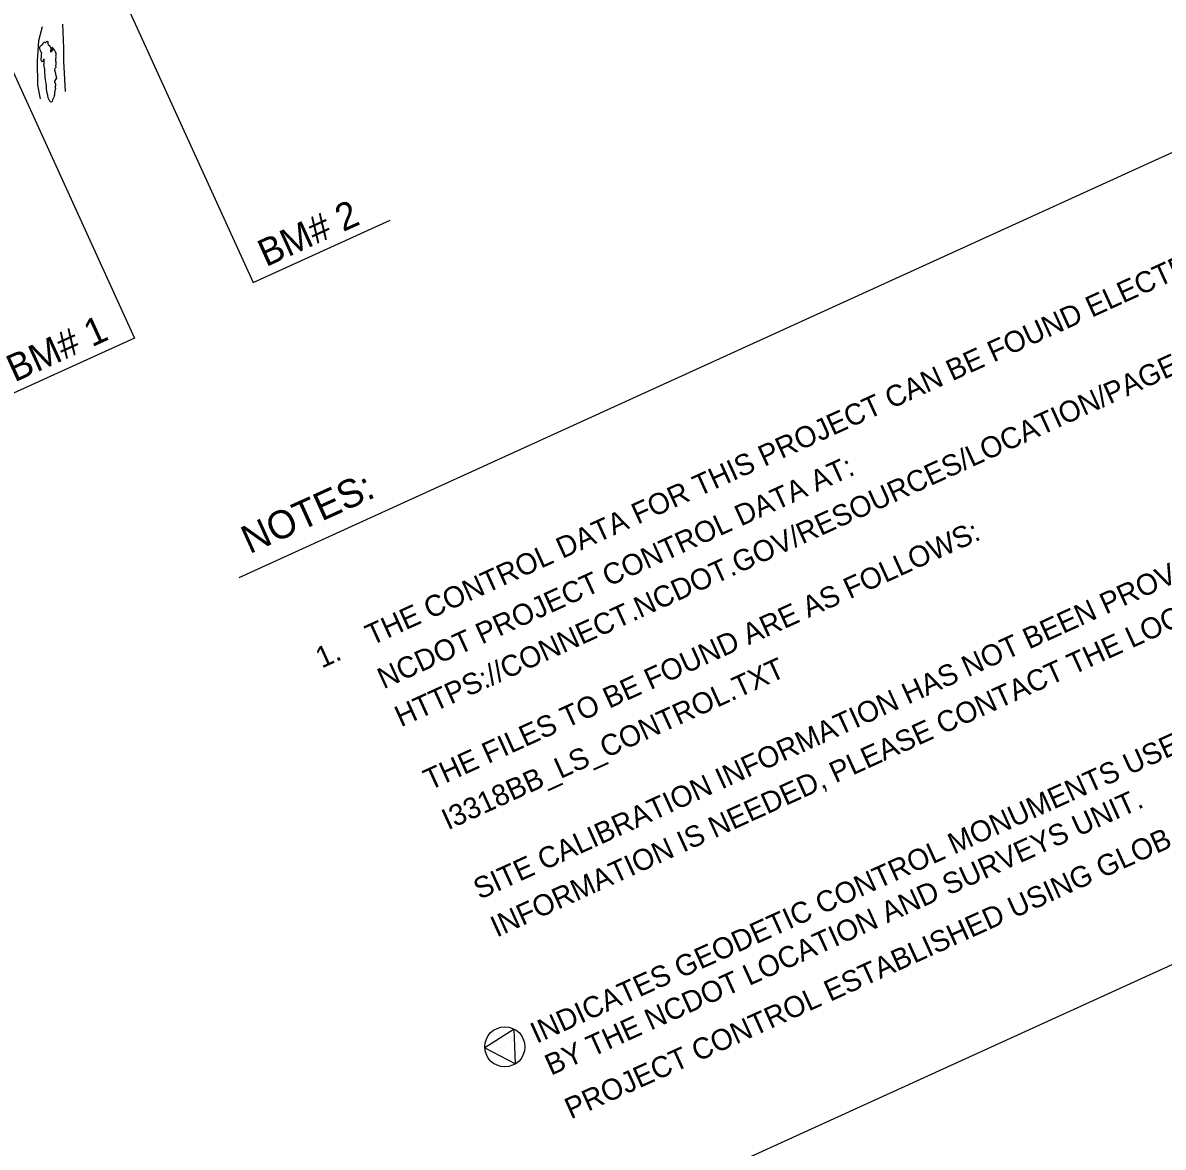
# Model space of a CAD drawing. Extents: x 2243531 to 2252747, y 658714 to 667210.
# Drawn here: x 2248974 to 2251073, y 661192 to 663262 of the extents above; entities that cross this region are included whole.
import ezdxf

# ---------------------------------------------------------------- set-up
doc = ezdxf.new("R2010")
doc.units = 0
for name, color, linetype in [('CTL Bench Mark Text', 7, 'Continuous'), ('CTL NGS Horizontal CELL', 7, 'Continuous'), ('CTL Sheet Border CELL', 7, 'Continuous'), ('CTL Sheet Notes CELL', 7, 'Continuous'), ('Exist Hydro Stream or Body of Water', 7, 'Continuous')]:
    doc.layers.add(name, color=color, linetype=linetype)

msp = doc.modelspace()

# ---------------------------------------------------------------- linework, layer by layer
at = {"layer": 'CTL NGS Horizontal CELL'}
for p, q in [((2249125.6, 663382.5), (2249398.3, 662784)), ((2248916.3, 663259.8), (2249179.7, 662681.7)), ((2249398.3, 662784), (2249650.2, 662898.7)), ((2249179.7, 662681.7), (2248943.9, 662574.3)), ((2249861.4, 661377.1), (2249861.4, 661377.1))]:
    msp.add_line(p, q, dxfattribs=at)
msp.add_lwpolyline([(2249824.5, 661375.2), (2249881.2, 661346), (2249878.3, 661409.9), (2249824.5, 661375.2)], dxfattribs=at)
msp.add_circle((2249861.4, 661377.1), 36.9, dxfattribs=at)
at = {"layer": 'CTL Sheet Border CELL'}
msp.add_lwpolyline([(2250569.7, 667061), (2243744.8, 663951.1), (2245921.8, 659173.7), (2252746.6, 662283.7)], close=True, dxfattribs=at)
at = {"layer": 'CTL Sheet Notes CELL'}
msp.add_line((2249372.3, 662241), (2251851.4, 663370.7), dxfattribs=at)
at = {"layer": 'Exist Hydro Stream or Body of Water'}
for points in [[(2249010.2, 663254.4), (2249003.4, 663229), (2249000.8, 663192), (2249001.5, 663147.2), (2249006.3, 663121.8)], [(2249052.9, 663135.6), (2249049.9, 663191.3), (2249050.1, 663215.3), (2249047.9, 663259.6)], [(2249036.1, 663160), (2249035.2, 663158.5), (2249034.3, 663157.6), (2249033.5, 663155.9), (2249032.7, 663154.1), (2249033, 663152.5), (2249033.8, 663151.1), (2249034.6, 663149.8), (2249034.6, 663148.4), (2249034.6, 663146.8), (2249034, 663144.9), (2249033.9, 663142.6), (2249034.3, 663141), (2249034.2, 663138.8), (2249033.4, 663137.3), (2249033.1, 663135.7), (2249032.7, 663133.6), (2249032.6, 663131.4), (2249032.6, 663129.5), (2249032.2, 663127.7), (2249031.3, 663125.3), (2249030.3, 663122.6), (2249029.3, 663120), (2249028.4, 663118), (2249027.5, 663116.5), (2249026.1, 663115.7), (2249024.3, 663117.6), (2249022.7, 663120.4), (2249021.3, 663123.6), (2249020.6, 663128.5), (2249019, 663132.6), (2249018.4, 663136.8), (2249018.2, 663140.1), (2249018.2, 663143.7), (2249017.8, 663146.6), (2249017.1, 663150.5), (2249016.6, 663154.2), (2249015.9, 663157.8), (2249015.3, 663161.5), (2249015.3, 663164.9), (2249015.2, 663169), (2249015.1, 663172.4), (2249014.7, 663175.9), (2249014.5, 663179.2), (2249013.7, 663182.3), (2249013.3, 663184.6), (2249013.7, 663186.6), (2249013.7, 663189.2), (2249013.7, 663191.1), (2249013.9, 663192.9), (2249013.8, 663194.5), (2249013.4, 663195), (2249012.5, 663194.4), (2249011.8, 663192.4), (2249011.1, 663190.8), (2249010.3, 663190.2), (2249009.5, 663190.9), (2249008.4, 663193.4), (2249008.3, 663196.3), (2249008.5, 663199.4), (2249008.9, 663203.2), (2249009.1, 663205.9), (2249008.3, 663208.2), (2249007.2, 663210.1), (2249006.5, 663212.2), (2249005.9, 663214.5), (2249006, 663217.4), (2249007, 663219.6), (2249009.2, 663221.1), (2249010.7, 663222.1), (2249011.7, 663223.7), (2249012.4, 663225.3), (2249013.8, 663226.4), (2249014.8, 663226.6), (2249015.6, 663225.5), (2249016.4, 663225.5), (2249017.2, 663226.6), (2249018.1, 663227.5), (2249018.9, 663228), (2249019.5, 663228), (2249020.3, 663226.1), (2249020.5, 663224.1), (2249021, 663221.6), (2249021.7, 663220.6), (2249022.7, 663220.1), (2249023.5, 663219.3), (2249024.5, 663218), (2249025.4, 663216.3), (2249025.7, 663214.2), (2249025.7, 663212.3), (2249025.4, 663211.2), (2249025.2, 663209.7), (2249025.6, 663208.8), (2249026.9, 663208.9), (2249028.1, 663209.8), (2249028.7, 663211.2), (2249029, 663212.7), (2249028.8, 663214.8), (2249028.5, 663216.9), (2249029.5, 663216), (2249031.1, 663213.3), (2249032.2, 663211.5), (2249033.1, 663210.1), (2249034.2, 663208.2), (2249035.2, 663205.9), (2249035.4, 663204.1), (2249035.2, 663202.1), (2249034.8, 663200.6), (2249035.3, 663198.7), (2249035.3, 663197.1), (2249034.8, 663195.6), (2249034.4, 663194), (2249034.4, 663192.2), (2249034.9, 663190.3), (2249035.4, 663188.4), (2249035.3, 663186.5), (2249034.9, 663184.8), (2249034.7, 663183.4), (2249035, 663181), (2249034.9, 663179.5), (2249034.2, 663178.6), (2249033.4, 663177.1), (2249033, 663175), (2249033.4, 663173), (2249034, 663171), (2249034.6, 663169.3), (2249034.7, 663167), (2249035, 663165.7), (2249035.5, 663163.8), (2249035.7, 663161.8), (2249036.1, 663160)]]:
    msp.add_lwpolyline(points, dxfattribs=at)

# ---------------------------------------------------------------- texts
at = {"layer": 'CTL Bench Mark Text'}
for s, p in [('BM# 2', (2249421.8, 662812)), ('BM# 1', (2248959.3, 662599.8))]:
    msp.add_text(s, height=50, rotation=24.4979, dxfattribs=at).set_placement(p)
at = {"layer": 'CTL Sheet Notes CELL'}
for s, height, rotation, p in [('1.    THE CONTROL DATA FOR THIS PROJECT CAN BE FOUND ELECTRONICALLY BY SELECTING', 38.739, 24.4979, (2249524.4, 662073.3)), ('HTTPS://CONNECT.NCDOT.GOV/RESOURCES/LOCATION/PAGES/DEFAULT.ASPX', 38.739, 24.4979, (2249670.1, 661965.2)), ('SITE CALIBRATION INFORMATION HAS NOT BEEN PROVIDED FOR THIS PROJECT. IF FURTHER', 38.739, 24.4979, (2249814.9, 661647.6)), ('INFORMATION IS NEEDED, PLEASE CONTACT THE LOCATION AND SURVEYS UNIT.', 38.739, 24.4979, (2249846.5, 661578.1)), ('NCDOT PROJECT CONTROL DATA AT:', 38.739, 24.4979, (2249638.3, 662035.1)), ('INDICATES GEODETIC CONTROL MONUMENTS USED OR SET FOR HORIZONTAL PROJECT CONTROL', 38.739, 24.3927, (2249919.9, 661382.5)), ('NOTES:', 51.65, 24.3927, (2249391.6, 662283.7)), ('THE FILES TO BE FOUND ARE AS FOLLOWS:', 38.739, 24.4979, (2249723.2, 661848.7)), ('I3318BB_LS_CONTROL.TXT', 38.739, 24.4979, (2249756.6, 661775.5)), ('PROJECT CONTROL ESTABLISHED USING GLOBAL POSITIONING SYSTEM.', 38.739, 24.3927, (2249982.9, 661243.5)), ('BY THE NCDOT LOCATION AND SURVEYS UNIT.', 38.739, 24.3927, (2249946.4, 661323.7))]:
    msp.add_text(s, height=height, rotation=rotation, dxfattribs=at).set_placement(p)

doc.saveas('drawing.dxf')
